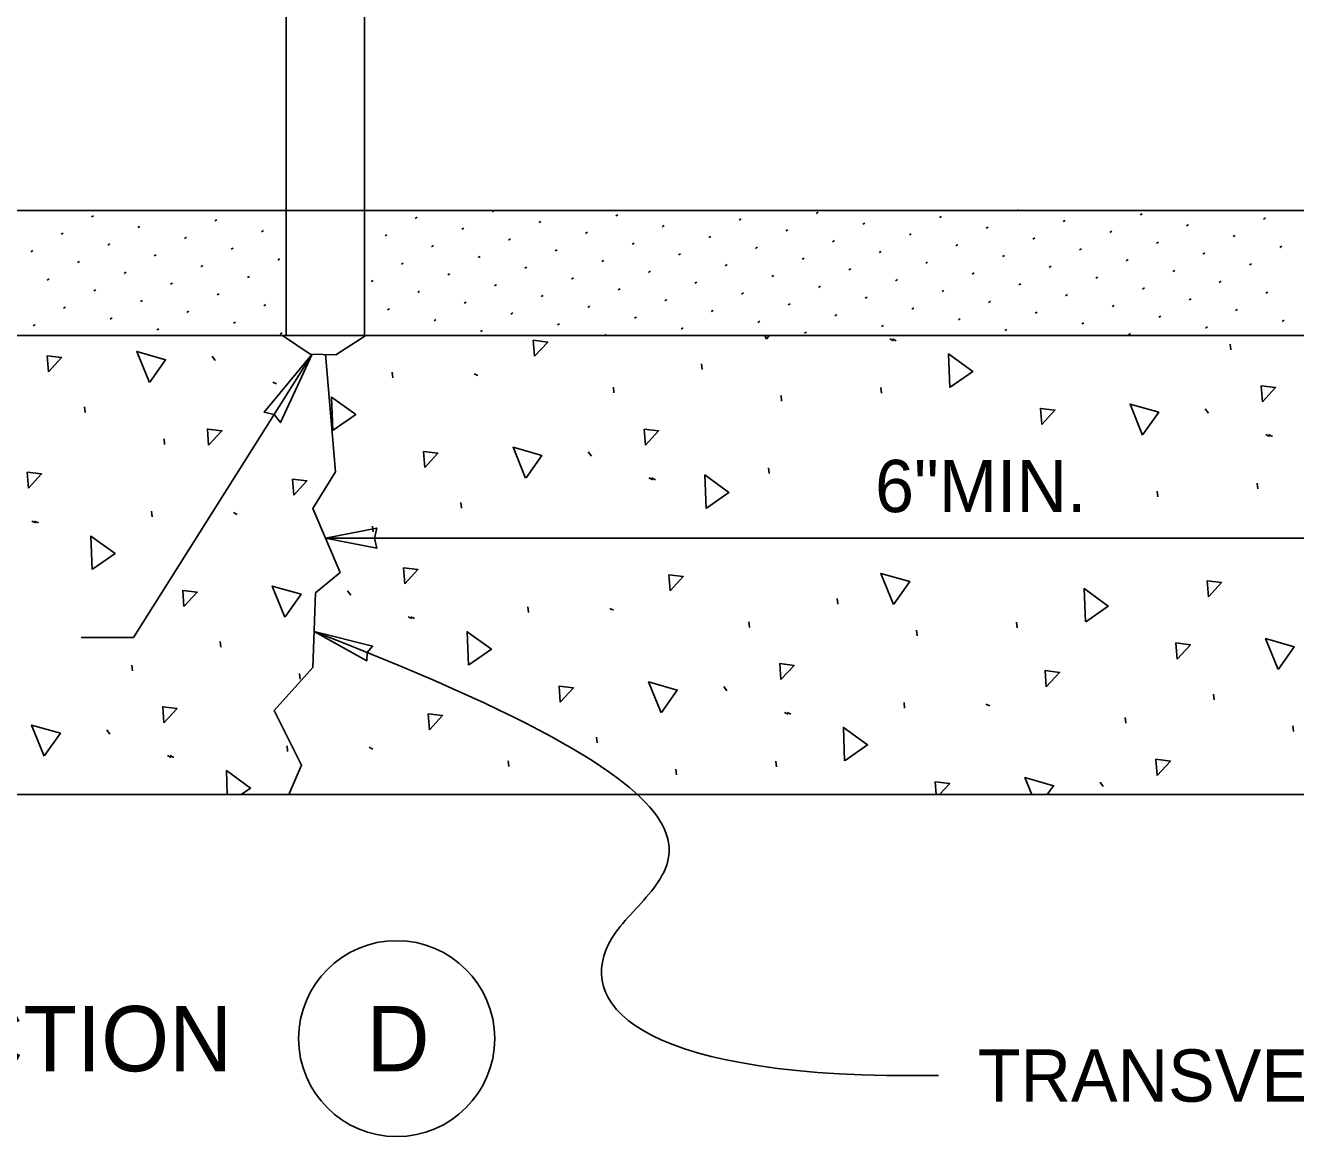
# Model space of a CAD drawing. Extents: x 99862 to 104211, y 98939 to 105076.
# Drawn here: x 101295.5 to 101684.2, y 103699.9 to 104040.2 of the extents above; entities that cross this region are included whole.
import ezdxf

# ---------------------------------------------------------------- set-up
doc = ezdxf.new("R2010")
doc.units = 0
for name, color, linetype in [('Level 1', 7, 'Continuous'), ('Level 14', 7, 'Continuous'), ('Level 15', 7, 'Continuous'), ('Level 2', 7, 'Continuous'), ('Level 20', 7, 'Continuous'), ('Level 3', 7, 'Continuous'), ('Level 4', 7, 'Continuous'), ('Level 8', 7, 'Continuous'), ('Level 9', 7, 'Continuous')]:
    doc.layers.add(name, color=color, linetype=linetype)

msp = doc.modelspace()

# ---------------------------------------------------------------- linework, layer by layer
at = {"layer": 'Level 1'}
msp.add_line((102063.85, 103945.23), (100698.76, 103945.23), dxfattribs=at)
msp.add_line((102063.85, 103945.23), (100698.76, 103945.23), dxfattribs=at)
msp.add_lwpolyline([(100169.63, 103804.62), (100694.77, 103804.62), (102647.84, 103804.62)], dxfattribs=at)
at = {"layer": 'Level 14'}
msp.add_lwpolyline([(101375.26, 104176.51), (101399.26, 104176.51), (101399.26, 103945.23), (101375.26, 103945.23)], close=True, dxfattribs=at)
msp.add_lwpolyline([(101399.26, 103945.23), (101399.26, 104176.5), (101375.26, 104176.5), (101375.26, 103945.23), (101399.26, 103945.23)], dxfattribs=at)
at = {"layer": 'Level 15'}
for p, q in [((101787.03, 103883.14), (101387.28, 103883.14)), ((101312.49, 103852.71), (101328.49, 103852.71)), ((101558.95, 103718.6), (101574.95, 103718.6))]:
    msp.add_line(p, q, dxfattribs=at)
msp.add_lwpolyline([(101328.49, 103852.71), (101383.23, 103939.47)], dxfattribs=at)
for points in [[(101383.23, 103939.47), (101368.52, 103921.76), (101371.61, 103921.06), (101373.57, 103918.57)], [(101387.28, 103883.14), (101403, 103880.06), (101402.28, 103883.14), (101403, 103886.23)], [(101383.85, 103854.55), (101401.71, 103850.07), (101400.05, 103848.16), (101399.96, 103845.63)]]:
    msp.add_lwpolyline(points, close=True, dxfattribs=at)
msp.add_open_spline([(101558.95, 103718.6), (101478.04, 103720.16), (101446.98, 103766.35), (101532.72, 103797.15), (101383.85, 103854.55)], degree=3, dxfattribs=at)
at = {"layer": 'Level 2'}
for p, q in [((101375.26, 103983.52), (101033.5, 103983.52)), ((101375.26, 103983.52), (101399.29, 103983.52)), ((101682.95, 103983.52), (101399.29, 103983.52)), ((101744.45, 103983.52), (101682.95, 103983.52))]:
    msp.add_line(p, q, dxfattribs=at)
at = {"layer": 'Level 20'}
msp.add_lwpolyline([(101374.14, 103945.23), (101382.58, 103939.48), (101390.42, 103939.35), (101399.66, 103945.23)], dxfattribs=at)
at = {"layer": 'Level 3'}
for p, q in [((101438.32, 103983.12), (101438.93, 103983.47)), ((101537.46, 103982.62), (101538.07, 103982.97)), ((101598.8, 103983.4), (101599.41, 103983.75)), ((101636.6, 103982.13), (101637.21, 103982.48)), ((101315.64, 103981.57), (101316.25, 103981.92)), ((101329.91, 103978.27), (101330.52, 103978.62)), ((101353.45, 103980.31), (101354.05, 103980.66)), ((101414.78, 103981.08), (101415.39, 103981.43)), ((101452.59, 103979.81), (101453.19, 103980.16)), ((101476.12, 103981.85), (101476.73, 103982.2)), ((101490.39, 103978.54), (101491, 103978.89)), ((101513.93, 103980.58), (101514.53, 103980.93)), ((101551.73, 103979.32), (101552.34, 103979.67)), ((101575.26, 103981.36), (101575.87, 103981.71)), ((101613.07, 103980.09), (101613.67, 103980.44)), ((101650.87, 103978.82), (101651.48, 103979.17)), ((101674.41, 103980.86), (101675.01, 103981.21)), ((101306.38, 103976.22), (101306.98, 103976.57)), ((101344.18, 103974.96), (101344.78, 103975.31)), ((101367.71, 103977), (101368.32, 103977.35)), ((101405.52, 103975.73), (101406.12, 103976.08)), ((101429.05, 103977.77), (101429.66, 103978.12)), ((101443.32, 103974.46), (101443.93, 103974.81)), ((101466.86, 103976.5), (101467.46, 103976.85)), ((101504.66, 103975.23), (101505.26, 103975.58)), ((101528.19, 103977.27), (101528.8, 103977.62)), ((101566, 103976.01), (101566.6, 103976.36)), ((101589.53, 103978.05), (101590.14, 103978.4)), ((101603.8, 103974.74), (101604.41, 103975.09)), ((101627.34, 103976.78), (101627.94, 103977.13)), ((101665.14, 103975.51), (101665.74, 103975.86)), ((101297.11, 103970.87), (101297.71, 103971.22)), ((101320.64, 103972.91), (101321.25, 103973.26)), ((101358.45, 103971.65), (101359.05, 103972)), ((101419.78, 103972.42), (101420.39, 103972.77)), ((101457.59, 103971.15), (101458.19, 103971.5)), ((101481.12, 103973.19), (101481.73, 103973.54)), ((101518.93, 103971.92), (101519.53, 103972.27)), ((101542.46, 103973.96), (101543.07, 103974.31)), ((101556.73, 103970.65), (101557.34, 103971)), ((101580.26, 103972.7), (101580.87, 103973.05)), ((101618.07, 103971.43), (101618.67, 103971.78)), ((101641.6, 103973.47), (101642.21, 103973.82)), ((101679.41, 103972.2), (101680.01, 103972.55)), ((101311.38, 103967.56), (101311.98, 103967.91)), ((101334.91, 103969.61), (101335.52, 103969.96)), ((101372.71, 103968.34), (101373.32, 103968.69)), ((101410.52, 103967.07), (101411.12, 103967.42)), ((101434.05, 103969.11), (101434.66, 103969.46)), ((101471.86, 103967.84), (101472.46, 103968.19)), ((101495.39, 103969.88), (101496, 103970.23)), ((101509.66, 103966.57), (101510.26, 103966.92)), ((101533.19, 103968.61), (101533.8, 103968.96)), ((101571, 103967.35), (101571.6, 103967.7)), ((101594.53, 103969.39), (101595.14, 103969.74)), ((101632.34, 103968.12), (101632.94, 103968.47)), ((101655.87, 103970.16), (101656.48, 103970.51)), ((101670.14, 103966.85), (101670.74, 103967.2)), ((101325.64, 103964.25), (101326.25, 103964.6)), ((101349.18, 103966.3), (101349.78, 103966.65)), ((101363.45, 103962.99), (101364.05, 103963.34)), ((101424.78, 103963.76), (101425.39, 103964.11)), ((101448.32, 103965.8), (101448.93, 103966.15)), ((101486.12, 103964.53), (101486.73, 103964.88)), ((101523.93, 103963.26), (101524.53, 103963.61)), ((101547.46, 103965.3), (101548.07, 103965.65)), ((101585.26, 103964.04), (101585.87, 103964.39)), ((101608.8, 103966.08), (101609.41, 103966.43)), ((101623.07, 103962.77), (101623.67, 103963.12)), ((101646.6, 103964.81), (101647.21, 103965.16)), ((101302.11, 103962.21), (101302.71, 103962.56)), ((101316.38, 103958.9), (101316.98, 103959.25)), ((101339.91, 103960.94), (101340.52, 103961.29)), ((101401.25, 103961.72), (101401.86, 103962.07)), ((101439.05, 103960.45), (101439.66, 103960.8)), ((101462.59, 103962.49), (101463.19, 103962.84)), ((101476.86, 103959.18), (101477.46, 103959.53)), ((101500.39, 103961.22), (101501, 103961.57)), ((101538.19, 103959.95), (101538.8, 103960.3)), ((101561.73, 103961.99), (101562.34, 103962.34)), ((101599.53, 103960.73), (101600.14, 103961.08)), ((101637.34, 103959.46), (101637.94, 103959.81)), ((101660.87, 103961.5), (101661.48, 103961.85)), ((101330.64, 103955.59), (101331.25, 103955.94)), ((101354.18, 103957.64), (101354.78, 103957.99)), ((101415.52, 103958.41), (101416.12, 103958.76)), ((101429.78, 103955.1), (101430.39, 103955.45)), ((101453.32, 103957.14), (101453.93, 103957.49)), ((101491.12, 103955.87), (101491.73, 103956.22)), ((101514.66, 103957.91), (101515.26, 103958.26)), ((101552.46, 103956.64), (101553.07, 103956.99)), ((101576, 103958.69), (101576.6, 103959.04)), ((101590.26, 103955.38), (101590.87, 103955.73)), ((101613.8, 103957.42), (101614.41, 103957.77)), ((101651.6, 103956.15), (101652.21, 103956.5)), ((101675.14, 103958.19), (101675.74, 103958.54)), ((101307.11, 103953.55), (101307.71, 103953.9)), ((101344.91, 103952.28), (101345.52, 103952.63)), ((101368.45, 103954.33), (101369.05, 103954.68)), ((101406.25, 103953.06), (101406.86, 103953.41)), ((101444.05, 103951.79), (101444.66, 103952.14)), ((101467.59, 103953.83), (101468.19, 103954.18)), ((101505.39, 103952.56), (101506, 103952.91)), ((101528.93, 103954.6), (101529.53, 103954.95)), ((101543.19, 103951.29), (101543.8, 103951.64)), ((101566.73, 103953.33), (101567.34, 103953.68)), ((101604.53, 103952.07), (101605.14, 103952.42)), ((101628.07, 103954.11), (101628.67, 103954.46)), ((101665.87, 103952.84), (101666.48, 103953.19)), ((101297.84, 103948.2), (101298.45, 103948.55)), ((101321.38, 103950.24), (101321.98, 103950.59)), ((101359.18, 103948.97), (101359.78, 103949.32)), ((101420.52, 103949.75), (101421.12, 103950.1)), ((101458.32, 103948.48), (101458.93, 103948.83)), ((101481.86, 103950.52), (101482.46, 103950.87)), ((101496.12, 103947.21), (101496.73, 103947.56)), ((101519.66, 103949.25), (101520.26, 103949.6)), ((101557.46, 103947.98), (101558.07, 103948.33)), ((101581, 103950.02), (101581.6, 103950.37)), ((101618.8, 103948.76), (101619.41, 103949.11)), ((101642.34, 103950.8), (101642.94, 103951.15)), ((101656.6, 103947.49), (101657.21, 103947.84)), ((101680.14, 103949.53), (101680.74, 103949.88)), ((101312.69, 103945.23), (101312.71, 103945.24)), ((101335.64, 103946.93), (101336.25, 103947.28)), ((101373.45, 103945.67), (101374.05, 103946.02)), ((101434.78, 103946.44), (101435.39, 103946.79)), ((101472.69, 103945.23), (101473.19, 103945.52)), ((101533.93, 103945.94), (101534.53, 103946.29)), ((101595.26, 103946.72), (101595.87, 103947.07)), ((101633.07, 103945.45), (101633.67, 103945.8))]:
    msp.add_line(p, q, dxfattribs=at)
at = {"layer": 'Level 4'}
for p, q in [((101559.98, 103944.18), (101561.13, 103943.61)), ((101560.8, 103944.18), (101561.94, 103943.62)), ((101664.43, 103940.88), (101664.24, 103942.62)), ((101352.57, 103938.87), (101353.53, 103937.57)), ((101502.61, 103934.85), (101502.43, 103936.59)), ((101407.92, 103932.27), (101407.73, 103934)), ((101432.82, 103933.52), (101433.97, 103932.95)), ((101371.14, 103930.95), (101372.29, 103930.38)), ((101475.59, 103927.66), (101475.41, 103929.4)), ((101557.48, 103927.54), (101557.3, 103929.28)), ((101526.91, 103925.09), (101526.72, 103926.83)), ((101313.77, 103921.62), (101313.59, 103923.36)), ((101656.57, 103922.79), (101657.52, 103921.49)), ((101338.07, 103911.86), (101337.89, 103913.6)), ((101675.14, 103914.87), (101676.28, 103914.3)), ((101675.95, 103914.87), (101677.1, 103914.31)), ((101467.73, 103909.56), (101468.68, 103908.26)), ((101523.07, 103902.95), (101522.89, 103904.69)), ((101486.3, 103901.64), (101487.45, 103901.07)), ((101487.12, 103901.65), (101488.27, 103901.08)), ((101642.07, 103895.78), (101641.88, 103897.52)), ((101672.64, 103898.23), (101672.46, 103899.97)), ((101428.93, 103892.31), (101428.75, 103894.05)), ((101334.24, 103889.73), (101334.05, 103891.47)), ((101359.15, 103890.98), (101360.3, 103890.42)), ((101297.46, 103888.42), (101298.61, 103887.85)), ((101298.28, 103888.42), (101299.43, 103887.85)), ((101401.91, 103885.12), (101401.73, 103886.86)), ((101394.05, 103867.02), (101395.01, 103865.73)), ((101449.4, 103860.42), (101449.21, 103862.16)), ((101544.09, 103863), (101543.91, 103864.74)), ((101412.62, 103859.1), (101413.77, 103858.54)), ((101413.44, 103859.11), (101414.59, 103858.54)), ((101474.31, 103861.67), (101475.45, 103861.11)), ((101517.07, 103855.81), (101516.89, 103857.55)), ((101568.39, 103853.24), (101568.21, 103854.98)), ((101598.97, 103855.69), (101598.78, 103857.43)), ((101355.26, 103849.77), (101355.07, 103851.51)), ((101328.24, 103842.58), (101328.05, 103844.32)), ((101379.55, 103840.01), (101379.37, 103841.75)), ((101509.21, 103837.71), (101510.17, 103836.42)), ((101659.25, 103833.69), (101659.07, 103835.43)), ((101564.56, 103831.11), (101564.37, 103832.85)), ((101589.46, 103832.36), (101590.61, 103831.8)), ((101527.78, 103829.79), (101528.93, 103829.23)), ((101528.6, 103829.8), (101529.75, 103829.23)), ((101632.23, 103826.5), (101632.05, 103828.24)), ((101320.38, 103824.48), (101321.33, 103823.19)), ((101683.55, 103823.93), (101683.36, 103825.67)), ((101375.72, 103817.88), (101375.54, 103819.62)), ((101400.63, 103819.14), (101401.78, 103818.57)), ((101470.41, 103820.46), (101470.23, 103822.2)), ((101338.95, 103816.57), (101340.09, 103816)), ((101339.76, 103816.57), (101340.91, 103816)), ((101443.39, 103813.27), (101443.21, 103815.01)), ((101494.71, 103810.7), (101494.53, 103812.44)), ((101525.29, 103813.15), (101525.1, 103814.89)), ((101624.37, 103808.4), (101625.33, 103807.11))]:
    msp.add_line(p, q, dxfattribs=at)
for points in [[(101451.28, 103938.85), (101450.91, 103943.76), (101455.32, 103943.23), (101451.28, 103938.85)], [(101522.24, 103944.06), (101521.77, 103945.23)], [(101523.08, 103945.23), (101522.35, 103944.19)], [(101333.41, 103930.83), (101329.55, 103940.33), (101338.34, 103937.82), (101333.52, 103930.97)], [(101302.51, 103934.09), (101302.14, 103939), (101306.55, 103938.47), (101302.51, 103934.09)], [(101578.38, 103929.35), (101578.01, 103939.59), (101585.41, 103934.23), (101578.54, 103929.44)], [(101674.06, 103924.91), (101673.68, 103929.82), (101678.09, 103929.29), (101674.06, 103924.91)], [(101389.55, 103916.12), (101389.17, 103926.37), (101396.58, 103921), (101389.7, 103916.21)], [(101637.4, 103914.75), (101633.54, 103924.24), (101642.34, 103921.74), (101637.51, 103914.88)], [(101606.51, 103918.01), (101606.13, 103922.92), (101610.54, 103922.39), (101606.51, 103918.01)], [(101351.54, 103911.68), (101351.17, 103916.59), (101355.58, 103916.06), (101351.54, 103911.68)], [(101485.22, 103911.68), (101484.85, 103916.59), (101489.26, 103916.06), (101485.22, 103911.68)], [(101417.67, 103904.78), (101417.3, 103909.69), (101421.7, 103909.16), (101417.67, 103904.78)], [(101448.56, 103901.52), (101444.71, 103911.02), (101453.5, 103908.51), (101448.68, 103901.66)], [(101296.39, 103898.46), (101296.01, 103903.37), (101300.42, 103902.84), (101296.39, 103898.46)], [(101377.61, 103896.31), (101377.23, 103901.22), (101381.64, 103900.69), (101377.61, 103896.31)], [(101503.78, 103892.29), (101503.4, 103902.53), (101510.8, 103897.17), (101503.93, 103892.38)], [(101315.87, 103873.59), (101315.5, 103883.83), (101322.9, 103878.47), (101316.03, 103873.68)], [(101411.55, 103869.15), (101411.17, 103874.06), (101415.58, 103873.53), (101411.55, 103869.15)], [(101492.77, 103867), (101492.39, 103871.91), (101496.8, 103871.38), (101492.77, 103867)], [(101561.18, 103862.87), (101557.32, 103872.36), (101566.11, 103869.85), (101561.29, 103863)], [(101657.54, 103865.2), (101657.16, 103870.11), (101661.57, 103869.58), (101657.54, 103865.2)], [(101343.99, 103862.24), (101343.62, 103867.15), (101348.03, 103866.62), (101343.99, 103862.24)], [(101374.89, 103858.98), (101371.03, 103868.48), (101379.82, 103865.97), (101375, 103859.12)], [(101619.87, 103857.5), (101619.49, 103867.75), (101626.89, 103862.38), (101620.02, 103857.59)], [(101431.03, 103844.28), (101430.65, 103854.52), (101438.06, 103849.15), (101431.18, 103844.37)], [(101647.99, 103846.16), (101647.61, 103851.07), (101652.02, 103850.54), (101647.99, 103846.16)], [(101678.88, 103842.9), (101675.02, 103852.4), (101683.82, 103849.89), (101679, 103843.04)], [(101526.7, 103839.84), (101526.33, 103844.75), (101530.74, 103844.21), (101526.7, 103839.84)], [(101607.92, 103837.69), (101607.55, 103842.6), (101611.96, 103842.07), (101607.92, 103837.69)], [(101490.05, 103829.67), (101486.19, 103839.17), (101494.98, 103836.66), (101490.16, 103829.81)], [(101459.15, 103832.93), (101458.78, 103837.84), (101463.19, 103837.31), (101459.15, 103832.93)], [(101337.87, 103826.61), (101337.49, 103831.52), (101341.9, 103830.99), (101337.87, 103826.61)], [(101419.09, 103824.46), (101418.71, 103829.37), (101423.12, 103828.84), (101419.09, 103824.46)], [(101301.21, 103816.45), (101297.35, 103825.94), (101306.15, 103823.43), (101301.32, 103816.58)], [(101546.19, 103814.97), (101545.81, 103825.21), (101553.22, 103819.84), (101546.34, 103815.05)], [(101641.86, 103810.52), (101641.49, 103815.44), (101645.9, 103814.9), (101641.86, 103810.52)], [(101357.25, 103804.62), (101356.98, 103811.98), (101364.38, 103806.62), (101361.52, 103804.62)], [(101574.24, 103804.62), (101573.94, 103808.53), (101578.35, 103808), (101575.23, 103804.62)], [(101603.47, 103804.62), (101601.35, 103809.86), (101610.14, 103807.35), (101608.22, 103804.62)]]:
    msp.add_lwpolyline(points, dxfattribs=at)
at = {"layer": 'Level 8'}
msp.add_lwpolyline([(101387.32, 103939.48), (101390.32, 103903.43), (101383.41, 103892.21), (101391.76, 103872.64), (101384.29, 103866.39), (101383.43, 103843.57), (101371.56, 103830.37), (101379.96, 103813.66), (101376.04, 103804.62)], dxfattribs=at)
at = {"layer": 'Level 9'}
msp.add_circle((101409.08, 103729.91), 30, dxfattribs=at)

# ---------------------------------------------------------------- texts
at = {"layer": 'Level 20'}
for s, height, p in [('6"MIN.', 16, (101555.52, 103891.14)), ('SECTION', 20, (101239.89, 103719.91)), ('D', 20, (101399.83, 103719.91)), ('TRANSVERSE CONTRACTION JOINT  ', 16, (101586.95, 103710.6))]:
    msp.add_text(s, height=height, dxfattribs=at).set_placement(p)

doc.saveas('drawing.dxf')
